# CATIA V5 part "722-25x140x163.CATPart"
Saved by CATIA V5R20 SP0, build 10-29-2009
Part number: 722-25x140x163
Definition: NONE
Nomenclature: 722-25x140x163
Source: Unknown
Description: 722-25x140x163
Bounding box of the stored display mesh (mm): x -12.5 to 12.5, y -12.5 to 12.5, z -128 to 35
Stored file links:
  C:\Users\Utente\Desktop\IO LAVORO\3D X SITO CF\X SITO\722\722-25x140x163.CATPart
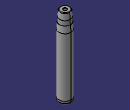
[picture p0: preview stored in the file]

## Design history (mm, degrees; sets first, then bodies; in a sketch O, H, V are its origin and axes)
Body1 "722-25x140x163" (main body)
  Solid1: solid without history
